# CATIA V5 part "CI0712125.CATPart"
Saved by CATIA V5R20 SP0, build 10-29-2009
Part number: CI0712125
Bounding box of the stored display mesh (mm): x -12 to 12, y -10.279 to 93, z -11.988 to 14.27
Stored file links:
  C:\Users\Raffaele\Desktop\3D X SITO CF\BOLEX\19-INCLINED ASSEMBLY REF_CI\CI0712125.CATPart
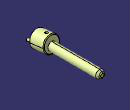
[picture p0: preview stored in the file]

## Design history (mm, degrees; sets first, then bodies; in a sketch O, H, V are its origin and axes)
Set1
  DatumSurface1 to DatumSurface16 "MANIFOLD_SOLID_BREP #379"
  DatumSurface17 to DatumSurface39 "MANIFOLD_SOLID_BREP #1096"
Body1 (main body)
